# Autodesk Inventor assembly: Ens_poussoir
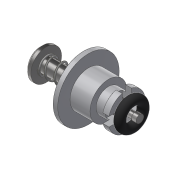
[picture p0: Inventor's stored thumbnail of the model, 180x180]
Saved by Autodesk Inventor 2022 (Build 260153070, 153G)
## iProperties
Created: 2018-06
Part Number: Ens_poussoir
Material: Générique
Document SubType Name: Assembly
Designer: Fabian Perrée
Mass: 5.90054 g
Surface Area: 24.3283 cm^2
Volume: 1.88874 cm^3
Density: 3.12406 g/cm^3
Author: Fabian Perrée
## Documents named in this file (5)
- C:\Users\Fabian\Google Drive\01_Giup\01_Clients\07_ENI\Manuscrit\Fichiers_exercice\Chapitre_06\Exercice_jeu_de_composant_en_contact\Composants\Ens_poussoir\Ens_poussoir.iam
- C:\Users\Fabian\Google Drive\01_Giup\01_Clients\07_ENI\Manuscrit\Fichiers_exercice\Capteur\Ens_poussoir\Composants\Guide.ipt
- C:\Users\Fabian\Google Drive\01_Giup\01_Clients\07_ENI\Manuscrit\Fichiers_exercice\Capteur\Ens_poussoir\Composants\Poussoir.ipt
- C:\Users\Fabian\Google Drive\01_Giup\01_Clients\07_ENI\Manuscrit\Fichiers_exercice\Capteur\Ens_poussoir\Composants\Joint.ipt
- C:\Users\Fabian\Google Drive\01_Giup\01_Clients\07_ENI\Manuscrit\Fichiers_exercice\Capteur\Capteur\Design Accelerator\Ressort de compression12.ipt
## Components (4 placed, 4 different names)
1. Guide:1 — Tangente:2, Placage:2
2. Poussoir:1 — Placage:1, Placage:2, Placage:3, Placage:4
3. Joint:1 — Tangente:2, Placage:1
4. Ressort de compression1:1 — Placage:3, Placage:4
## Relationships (5: Mate 4, Tangent 1)
- Tangente:2: Guide:1 ↔ Joint:1
- Placage:1 [Mate]: Poussoir:1 ↔ Joint:1
- Placage:2 [Mate]: Guide:1 ↔ Poussoir:1
- Placage:3 [Mate]: Poussoir:1 ↔ Ressort de compression1:1
- Placage:4 [Mate]: Poussoir:1 ↔ Ressort de compression1:1
